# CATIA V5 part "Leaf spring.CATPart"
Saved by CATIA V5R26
Part number: Part1
Material "Steel": density 7860 kg/m3, Young's modulus 2e+11 Pa, Poisson ratio 0.266, thermal expansion 1.17e-05 1/K
Bounding box of the stored display mesh (mm): x 0 to 6, y -52.464 to 52.464, z -1 to 10.425
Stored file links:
  D:\_Deepak\CATIA\New Chapter\C19 FEA\Tutorial\TUT03\Leaf spring.CATPart
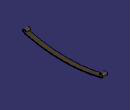
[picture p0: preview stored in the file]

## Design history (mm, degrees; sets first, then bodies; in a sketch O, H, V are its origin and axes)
Body1 (main body), material "Steel"
  Sketch1 on yz-plane, origin (0, 0, 0), H (0, 1, 0), V (0, 0, 1)
    arc A1 centre (0, 199) radius 199 from (-50.3797, 6.4828) to (50.3797, 6.4828) ccw
    point P1 (0, 199)
    arc A2 centre (0, 199) radius 200 from (-50.6329, 5.5154) to (50.6329, 5.5154) ccw
    arc A3 centre (-50, 7.9339) radius 2.5 from (-47.5, 7.9339) to (-50.6329, 5.5154) ccw
    point P2 (-50, 7.9339)
    arc A4 centre (50, 7.9339) radius 2.5 from (47.5, 7.9339) to (50.6329, 5.5154) cw
    arc A5 centre (-50, 7.9339) radius 1.5 from (-48.5, 7.9339) to (-50.3797, 6.4828) ccw
    point P4 (50, 7.9339)
    arc A6 centre (50, 7.9339) radius 1.5 from (48.5, 7.9339) to (50.3797, 6.4828) cw
    point P8 (50.3797, 6.4828)
    line L1 (48.5, 7.9339) -> (47.5, 7.9339)
    point P10 (-47.5, 7.9339)
    point P11 (50.3797, 6.4828)
    line L2 (-47.5, 7.9339) -> (-48.5, 7.9339)
    distance A1 A2 = 1
    distance P4 P2 = 100
    radius A3 = 2.5
    radius A2 = 200
    coincidence: A1 O, P1 V, A6 P8, L1 P10, A1 P11, L1 L2, L2 P2
    concentricity: A1 A2
    tangency: A3 A2, A5 A1
    symmetry: A3 A4 V, A5 A6 V
    horizontal: L1 H, L2 H
  Pad1: profile Sketch1, direction (1, 0, 0), length 6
